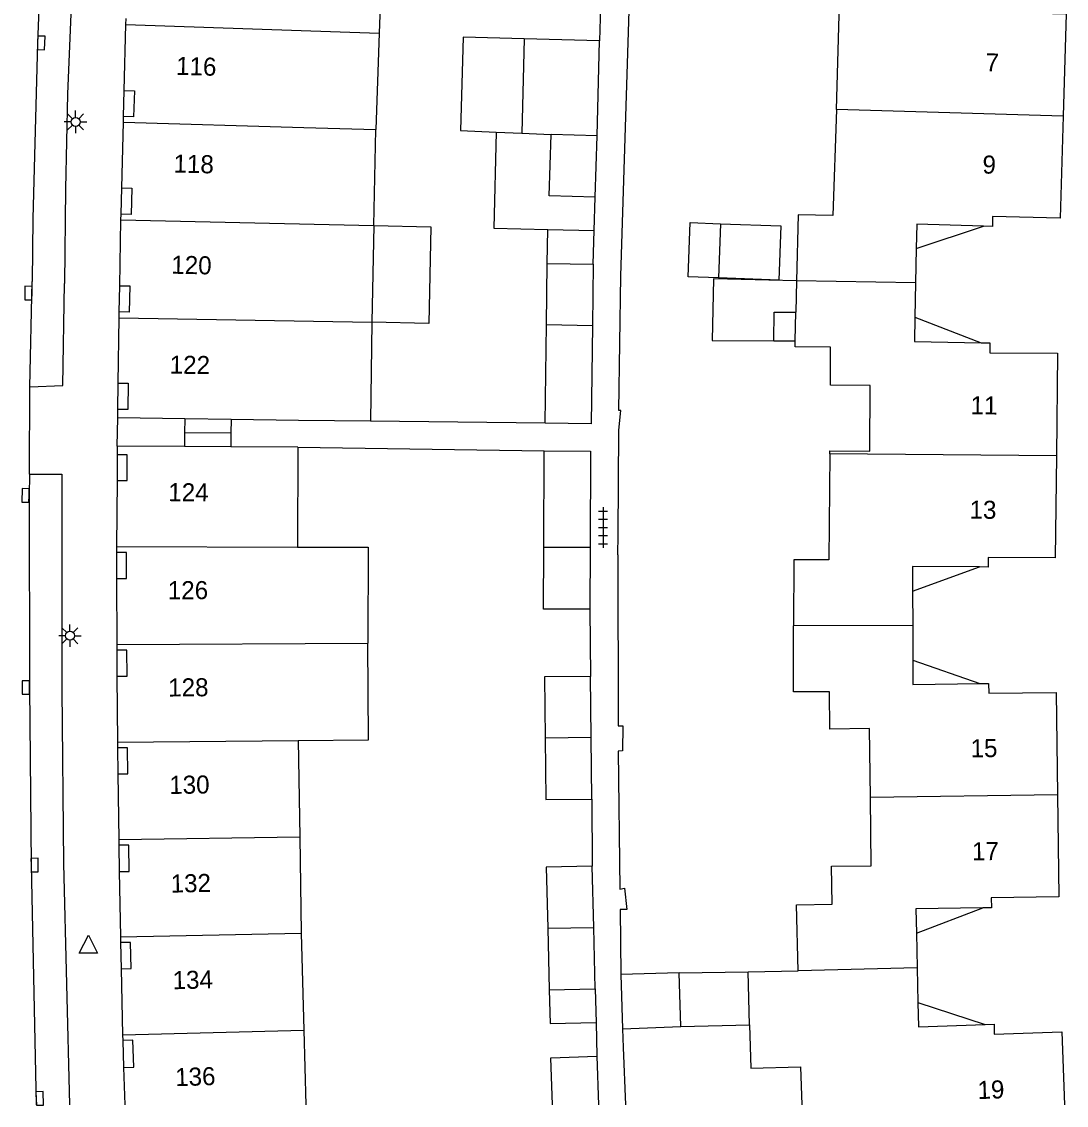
# Model space of a CAD drawing. Extents: x 124000 to 128010, y 398999 to 403000.
# Drawn here: x 126564.4 to 126622.2, y 399000 to 399060 of the extents above; entities that cross this region are included whole.
import ezdxf

# ---------------------------------------------------------------- set-up
doc = ezdxf.new("R2010")
doc.units = 0
for name, color, linetype in [('gg-afsc-erfafscheiding', 7, 'Continuous'), ('gg-afsc-muur', 7, 'Continuous'), ('gg-anno-huisnummerreeks BGT', 7, 'Continuous'), ('gg-bbg-bijgebouw', 7, 'Continuous'), ('gg-bbg-gedigitaliseerde bebouwing', 7, 'Continuous'), ('gg-bbg-gedigitaliseerde bijgebouw', 7, 'Continuous'), ('gg-bbg-hoofdgebouw', 7, 'Continuous'), ('gg-bbg-luifel en loopbrug', 7, 'Continuous'), ('gg-bbg-onder overbouw', 7, 'Continuous'), ('gg-bbg-pand overbouw', 7, 'Continuous'), ('gg-bbg-tussenscheiding', 7, 'Continuous'), ('gg-bbg-tussenscheiding niveau 01', 7, 'Continuous'), ('gg-knt-verharding', 7, 'Continuous'), ('gg-knt-verharding nz', 7, 'Continuous'), ('gt-symb-kolk', 7, 'Continuous'), ('gt-symb-lichtmast', 7, 'Continuous'), ('gt-symb-tegel verharding', 7, 'Continuous'), ('gt-symb-waterafsluiter', 7, 'Continuous')]:
    doc.layers.add(name, color=color, linetype=linetype)

# ---------------------------------------------------------------- blocks, each defined once
blk = doc.blocks.new('gt0-KOLK')
at = {"layer": 'gt-symb-kolk'}
blk.add_lwpolyline([(0, 0), (0.375, 0), (0.375, 0.4), (-0.375, 0.4), (-0.375, 0), (0, 0)], dxfattribs=at)
blk = doc.blocks.new('gt0-WAFSL')
at = {"layer": 'gt-symb-waterafsluiter'}
for p, q in [((-0.5, -0.333), (0, 0.667)), ((0, 0.667), (0.5, -0.333)), ((0.5, -0.333), (-0.5, -0.333))]:
    blk.add_line(p, q, dxfattribs=at)
blk = doc.blocks.new('gt0-LMAST')
at = {"layer": 'gt-symb-lichtmast'}
for p, q in [((-0.005, 0.246), (-0.005, 0.621)), ((-0.182, 0.173), (-0.447, 0.438)), ((0.172, 0.173), (0.437, 0.438)), ((-0.255, -0.004), (-0.63, -0.004)), ((-0.182, -0.181), (-0.447, -0.446)), ((-0.005, -0.254), (-0.005, -0.629)), ((0.437, -0.446), (0.172, -0.181)), ((0.245, -0.004), (0.62, -0.004))]:
    blk.add_line(p, q, dxfattribs=at)
blk.add_circle((-0.005, -0.004), 0.25, dxfattribs=at)
blk = doc.blocks.new('gt0-TEG1')
at = {"layer": 'gt-symb-tegel verharding'}
for p, q in [((-1.125, 0), (1.125, 0)), ((-0.9, -0.25), (-0.9, 0.25)), ((-0.45, -0.25), (-0.45, 0.25)), ((0, -0.25), (0, 0.25)), ((0.45, -0.25), (0.45, 0.25)), ((0.9, -0.25), (0.9, 0.25))]:
    blk.add_line(p, q, dxfattribs=at)

msp = doc.modelspace()

# ---------------------------------------------------------------- linework, layer by layer
at = {"layer": 'gg-afsc-erfafscheiding'}
for p, q in [((126596.442, 399060.81), (126596.39, 399058.933)), ((126597.471, 399037.357), (126597.577, 399038.451)), ((126597.4, 399030.467), (126597.42, 399031.569)), ((126595.856, 399027.447), (126595.89, 399023.725)), ((126597.678, 399020.993), (126597.674, 399019.598)), ((126595.961, 399016.937), (126595.989, 399013.218)), ((126597.779, 399011.998), (126597.898, 399010.824)), ((126596.201, 399004.563), (126596.247, 399002.695)), ((126597.665, 399004.22), (126597.706, 399003.174))]:
    msp.add_line(p, q, dxfattribs=at)
msp.add_lwpolyline([(126597.566, 399045.913), (126598.094, 399062.376), (126598.818, 399078.831)], dxfattribs=at)
at = {"layer": 'gg-afsc-muur'}
for p, q in [((126569.688, 399036.475), (126569.718, 399038.052)), ((126593.379, 399037.745), (126583.718, 399037.871)), ((126597.42, 399031.569), (126597.471, 399037.357)), ((126579.685, 399036.418), (126593.327, 399036.211)), ((126597.706, 399003.174), (126597.826, 399000))]:
    msp.add_line(p, q, dxfattribs=at)
for points in [[(126597.577, 399038.451), (126597.469, 399038.454), (126597.566, 399045.913)], [(126597.4, 399030.467), (126597.42, 399020.989), (126597.678, 399020.993)], [(126597.674, 399019.598), (126597.436, 399019.588), (126597.517, 399011.944), (126597.779, 399011.998)], [(126597.898, 399010.824), (126597.537, 399010.822), (126597.577, 399007.216)]]:
    msp.add_lwpolyline(points, dxfattribs=at)
at = {"layer": 'gg-bbg-bijgebouw'}
for p, q in [((126596.152, 399050.27), (126596.258, 399053.657)), ((126593.452, 399043.207), (126593.498, 399046.6)), ((126593.498, 399046.6), (126596.044, 399046.566)), ((126596.044, 399046.566), (126595.998, 399043.166)), ((126593.379, 399037.745), (126593.452, 399043.207)), ((126593.307, 399030.863), (126593.327, 399036.211)), ((126595.868, 399030.858), (126595.856, 399027.447)), ((126595.925, 399020.337), (126595.89, 399023.725)), ((126595.961, 399016.937), (126595.925, 399020.337)), ((126596.071, 399009.829), (126595.989, 399013.218)), ((126593.526, 399009.778), (126593.609, 399006.369)), ((126596.154, 399006.431), (126596.071, 399009.829)), ((126600.802, 399007.316), (126597.577, 399007.216)), ((126597.577, 399007.216), (126597.665, 399004.22)), ((126600.895, 399004.337), (126600.802, 399007.316)), ((126593.609, 399006.369), (126596.154, 399006.431)), ((126597.665, 399004.22), (126600.895, 399004.337)), ((126596.247, 399002.695), (126596.34, 399000))]:
    msp.add_line(p, q, dxfattribs=at)
for points in [[(126596.152, 399050.27), (126593.608, 399050.349), (126593.714, 399053.73)], [(126595.998, 399043.166), (126595.924, 399037.712), (126593.379, 399037.745)], [(126593.327, 399036.211), (126595.888, 399036.201), (126595.868, 399030.858)], [(126595.856, 399027.447), (126593.294, 399027.456), (126593.307, 399030.863)], [(126595.89, 399023.725), (126593.344, 399023.698), (126593.38, 399020.313)], [(126593.38, 399020.313), (126593.416, 399016.91), (126595.961, 399016.937)], [(126595.989, 399013.218), (126593.444, 399013.157), (126593.526, 399009.778)], [(126593.792, 399000), (126593.702, 399002.608), (126596.247, 399002.695)]]:
    msp.add_lwpolyline(points, dxfattribs=at)
at = {"layer": 'gg-bbg-gedigitaliseerde bebouwing'}
for p, q in [((126584.382, 399064.678), (126584.199, 399059.355)), ((126584.199, 399059.355), (126584.016, 399054.012)), ((126583.9, 399048.692), (126584.016, 399054.012)), ((126583.9, 399048.692), (126583.789, 399043.343)), ((126583.789, 399043.343), (126583.718, 399037.871)), ((126579.685, 399036.418), (126579.678, 399030.893)), ((126579.71, 399020.185), (126579.794, 399014.844)), ((126579.794, 399014.844), (126579.877, 399009.512)), ((126607.388, 399007.428), (126607.303, 399011.087)), ((126579.877, 399009.512), (126580.017, 399004.145)), ((126604.634, 399007.36), (126607.388, 399007.428)), ((126604.706, 399004.431), (126604.634, 399007.36)), ((126580.017, 399004.145), (126580.126, 399000))]:
    msp.add_line(p, q, dxfattribs=at)
for points in [[(126579.678, 399030.893), (126583.583, 399030.884), (126583.571, 399025.562)], [(126579.71, 399020.185), (126583.61, 399020.213), (126583.571, 399025.562)], [(126604.706, 399004.431), (126604.765, 399002.042), (126607.514, 399002.11), (126607.598, 399000)]]:
    msp.add_lwpolyline(points, dxfattribs=at)
at = {"layer": 'gg-bbg-gedigitaliseerde bijgebouw'}
for p, q in [((126592.221, 399059.037), (126592.09, 399053.807)), ((126596.39, 399058.933), (126592.221, 399059.037)), ((126596.258, 399053.657), (126596.39, 399058.933)), ((126592.09, 399053.807), (126593.714, 399053.73)), ((126603.086, 399048.799), (126602.981, 399045.796))]:
    msp.add_line(p, q, dxfattribs=at)
for points in [[(126603.086, 399048.799), (126606.432, 399048.682), (126606.327, 399045.678), (126602.981, 399045.796)], [(126607.305, 399045.639), (126602.713, 399045.742), (126602.637, 399042.323), (126606.052, 399042.312)], [(126606.052, 399042.312), (126606.057, 399043.898), (126607.266, 399043.898)]]:
    msp.add_lwpolyline(points, dxfattribs=at)
at = {"layer": 'gg-bbg-hoofdgebouw'}
for p, q in [((126570.174, 399059.838), (126570.182, 399060.158)), ((126570.08, 399056.176), (126570.174, 399059.838)), ((126570.029, 399054.414), (126570.037, 399054.734)), ((126569.94, 399050.776), (126570.029, 399054.414)), ((126569.896, 399049.003), (126569.902, 399049.323)), ((126569.828, 399045.362), (126569.896, 399049.003)), ((126613.933, 399047.424), (126613.896, 399045.515)), ((126613.896, 399045.515), (126613.859, 399043.616)), ((126569.793, 399043.591), (126569.797, 399043.914)), ((126607.231, 399042.312), (126607.266, 399043.898)), ((126569.75, 399039.97), (126569.793, 399043.591)), ((126569.718, 399038.052), (126569.721, 399038.516)), ((126573.428, 399037.997), (126569.718, 399038.052)), ((126569.688, 399036.475), (126569.685, 399036.006)), ((126573.407, 399036.454), (126569.688, 399036.475)), ((126579.685, 399036.418), (126575.978, 399036.439)), ((126569.688, 399034.57), (126569.655, 399030.915)), ((126569.655, 399030.915), (126569.652, 399030.595)), ((126569.655, 399029.153), (126569.658, 399025.495)), ((126613.731, 399028.458), (126613.736, 399026.547)), ((126613.736, 399026.547), (126613.741, 399024.637)), ((126569.658, 399025.495), (126569.658, 399025.175)), ((126569.673, 399023.739), (126569.698, 399020.089)), ((126569.698, 399020.089), (126569.7, 399019.769)), ((126569.727, 399018.331), (126569.773, 399014.701)), ((126569.773, 399014.701), (126569.777, 399014.381)), ((126569.799, 399012.926), (126569.869, 399009.307)), ((126569.869, 399009.307), (126569.875, 399008.987)), ((126613.94, 399009.511), (126613.982, 399007.593)), ((126569.906, 399007.537), (126569.989, 399003.886)), ((126613.982, 399007.593), (126614.024, 399005.674)), ((126569.989, 399003.886), (126569.996, 399003.566)), ((126570.045, 399002.08), (126570.106, 399000))]:
    msp.add_line(p, q, dxfattribs=at)
for points in [[(126609.525, 399055.113), (126609.677, 399061.003), (126607.715, 399061.061), (126607.872, 399064.718)], [(126618.024, 399061.072), (126618.511, 399061.057), (126618.487, 399060.505), (126622.242, 399060.419), (126622.071, 399054.755)], [(126609.525, 399055.113), (126609.311, 399049.252), (126607.387, 399049.288), (126607.305, 399045.639)], [(126622.071, 399054.755), (126621.901, 399049.098), (126618.153, 399049.194), (126618.15, 399048.648), (126617.657, 399048.663)], [(126617.657, 399048.663), (126613.959, 399048.774), (126613.933, 399047.424)], [(126613.859, 399043.616), (126613.833, 399042.266), (126617.533, 399042.208)], [(126609.15, 399036.062), (126609.152, 399036.22), (126611.361, 399036.208), (126611.379, 399039.84), (126609.186, 399039.857), (126609.191, 399041.953), (126607.223, 399041.98), (126607.231, 399042.312)], [(126617.533, 399042.208), (126618.011, 399042.2), (126618.006, 399041.651), (126621.747, 399041.634), (126621.69, 399035.949)], [(126583.718, 399037.871), (126579.718, 399037.903), (126575.997, 399037.958)], [(126609.15, 399036.062), (126609.092, 399030.175), (126607.147, 399030.19), (126607.144, 399026.53)], [(126621.69, 399035.949), (126621.633, 399030.289), (126617.923, 399030.309), (126617.908, 399029.785), (126617.428, 399029.788)], [(126617.428, 399029.788), (126613.728, 399029.808), (126613.731, 399028.458)], [(126611.391, 399017.03), (126611.336, 399020.85), (126609.146, 399020.799), (126609.124, 399022.876), (126607.141, 399022.865), (126607.144, 399026.53)], [(126613.741, 399024.637), (126613.744, 399023.287), (126617.444, 399023.337)], [(126617.444, 399023.337), (126617.924, 399023.344), (126617.948, 399022.793), (126621.676, 399022.844), (126621.752, 399017.173)], [(126607.303, 399011.087), (126609.277, 399011.112), (126609.234, 399013.22), (126611.439, 399013.242), (126611.391, 399017.03)], [(126621.752, 399017.173), (126621.828, 399011.514), (126618.089, 399011.46), (126618.092, 399010.913), (126617.611, 399010.907)], [(126617.611, 399010.907), (126613.911, 399010.861), (126613.94, 399009.511)], [(126614.024, 399005.674), (126614.054, 399004.324), (126617.752, 399004.446)], [(126617.752, 399004.446), (126618.238, 399004.462), (126618.255, 399003.914), (126621.998, 399004.047), (126622.132, 399000)]]:
    msp.add_lwpolyline(points, dxfattribs=at)
at = {"layer": 'gg-bbg-luifel en loopbrug'}
for p, q in [((126590.677, 399053.874), (126592.09, 399053.807)), ((126596.098, 399048.418), (126596.152, 399050.27)), ((126613.933, 399047.424), (126617.657, 399048.663)), ((126593.498, 399046.6), (126593.524, 399048.482)), ((126593.524, 399048.482), (126596.098, 399048.418)), ((126596.044, 399046.566), (126596.098, 399048.418)), ((126613.859, 399043.616), (126617.533, 399042.208)), ((126606.052, 399042.312), (126607.231, 399042.312)), ((126613.731, 399028.458), (126617.428, 399029.788)), ((126613.741, 399024.637), (126617.444, 399023.337)), ((126613.94, 399009.511), (126617.611, 399010.907)), ((126600.802, 399007.316), (126604.634, 399007.36)), ((126596.154, 399006.431), (126596.201, 399004.563)), ((126614.024, 399005.674), (126617.752, 399004.446)), ((126600.895, 399004.337), (126604.706, 399004.431))]:
    msp.add_line(p, q, dxfattribs=at)
for points in [[(126592.221, 399059.037), (126588.84, 399059.131), (126588.695, 399053.968), (126590.677, 399053.874)], [(126590.677, 399053.874), (126590.545, 399048.556), (126593.524, 399048.482)], [(126583.9, 399048.692), (126587.052, 399048.621), (126586.935, 399043.273), (126583.789, 399043.343)], [(126602.981, 399045.796), (126601.307, 399045.854), (126601.413, 399048.858), (126603.086, 399048.799)], [(126593.609, 399006.369), (126593.654, 399004.501), (126596.201, 399004.563)]]:
    msp.add_lwpolyline(points, dxfattribs=at)
at = {"layer": 'gg-bbg-onder overbouw'}
for p, q in [((126575.997, 399037.958), (126573.428, 399037.997)), ((126575.978, 399036.439), (126573.407, 399036.454))]:
    msp.add_line(p, q, dxfattribs=at)
for points in [[(126570.08, 399056.176), (126570.64, 399056.159), (126570.587, 399054.718), (126570.037, 399054.734)], [(126569.94, 399050.776), (126570.5, 399050.761), (126570.452, 399049.309), (126569.902, 399049.323)], [(126569.828, 399045.362), (126570.388, 399045.35), (126570.347, 399043.902), (126569.797, 399043.914)], [(126569.75, 399039.97), (126570.3, 399039.959), (126570.281, 399038.505), (126569.721, 399038.516)], [(126569.688, 399034.57), (126570.238, 399034.571), (126570.235, 399036.007), (126569.685, 399036.006)], [(126569.655, 399029.153), (126570.205, 399029.154), (126570.202, 399030.596), (126569.652, 399030.595)], [(126569.673, 399023.739), (126570.233, 399023.745), (126570.218, 399025.181), (126569.658, 399025.175)], [(126569.727, 399018.331), (126570.277, 399018.341), (126570.26, 399019.78), (126569.7, 399019.769)], [(126569.799, 399012.926), (126570.359, 399012.934), (126570.337, 399014.389), (126569.777, 399014.381)], [(126569.906, 399007.537), (126570.456, 399007.549), (126570.425, 399008.999), (126569.875, 399008.987)], [(126570.045, 399002.08), (126570.605, 399002.098), (126570.556, 399003.584), (126569.996, 399003.566)]]:
    msp.add_lwpolyline(points, dxfattribs=at)
at = {"layer": 'gg-bbg-pand overbouw'}
for p, q in [((126570.037, 399054.734), (126570.08, 399056.176)), ((126569.902, 399049.323), (126569.94, 399050.776)), ((126569.797, 399043.914), (126569.828, 399045.362)), ((126569.721, 399038.516), (126569.75, 399039.97)), ((126573.428, 399037.997), (126573.417, 399037.225)), ((126575.997, 399037.958), (126575.987, 399037.192)), ((126573.417, 399037.225), (126573.407, 399036.454)), ((126575.987, 399037.192), (126575.978, 399036.439)), ((126569.685, 399036.006), (126569.688, 399034.57)), ((126569.652, 399030.595), (126569.655, 399029.153)), ((126569.658, 399025.175), (126569.673, 399023.739)), ((126569.7, 399019.769), (126569.727, 399018.331)), ((126569.777, 399014.381), (126569.799, 399012.926)), ((126569.875, 399008.987), (126569.906, 399007.537)), ((126569.996, 399003.566), (126570.045, 399002.08))]:
    msp.add_line(p, q, dxfattribs=at)
at = {"layer": 'gg-bbg-tussenscheiding'}
for p, q in [((126570.174, 399059.838), (126584.199, 399059.355)), ((126622.071, 399054.755), (126609.525, 399055.113)), ((126570.029, 399054.414), (126580.024, 399054.13)), ((126580.024, 399054.13), (126584.016, 399054.012)), ((126596.258, 399053.657), (126593.714, 399053.73)), ((126569.896, 399049.003), (126583.9, 399048.692)), ((126607.305, 399045.639), (126607.266, 399043.898)), ((126613.896, 399045.515), (126607.305, 399045.639)), ((126569.793, 399043.591), (126583.789, 399043.343)), ((126593.452, 399043.207), (126595.998, 399043.166)), ((126621.69, 399035.949), (126609.15, 399036.062)), ((126569.655, 399030.915), (126579.678, 399030.893)), ((126595.868, 399030.858), (126593.307, 399030.863)), ((126613.736, 399026.547), (126607.144, 399026.53)), ((126569.658, 399025.495), (126583.571, 399025.562)), ((126569.698, 399020.089), (126579.71, 399020.185)), ((126595.925, 399020.337), (126593.38, 399020.313)), ((126621.752, 399017.173), (126611.391, 399017.03)), ((126569.773, 399014.701), (126579.794, 399014.844)), ((126593.526, 399009.778), (126596.071, 399009.829)), ((126569.869, 399009.307), (126579.877, 399009.512)), ((126613.982, 399007.593), (126607.388, 399007.428)), ((126569.989, 399003.886), (126580.017, 399004.145))]:
    msp.add_line(p, q, dxfattribs=at)
at = {"layer": 'gg-bbg-tussenscheiding niveau 01'}
msp.add_line((126575.987, 399037.192), (126573.417, 399037.225), dxfattribs=at)
at = {"layer": 'gg-knt-verharding'}
msp.add_line((126564.837, 399034.922), (126564.856, 399039.765), dxfattribs=at)
for points in [[(126567.754, 399102.809), (126569.494, 399102.609), (126568.412, 399086.646), (126567.575, 399071.509), (126566.943, 399055.965), (126566.823, 399050.729), (126566.765, 399045.491)], [(126564.856, 399039.765), (126566.686, 399039.832), (126566.765, 399045.491)], [(126564.837, 399034.922), (126566.619, 399034.933), (126566.625, 399023.009), (126566.72, 399013.37), (126567.044, 399000)]]:
    msp.add_lwpolyline(points, dxfattribs=at)
at = {"layer": 'gg-knt-verharding nz'}
msp.add_line((126564.856, 399039.765), (126564.986, 399045.601), dxfattribs=at)
for points in [[(126567.754, 399102.809), (126567.488, 399099.583), (126566.638, 399086.898), (126565.782, 399071.857), (126565.283, 399058.814), (126565.014, 399049.089), (126564.986, 399045.601)], [(126564.837, 399034.922), (126564.807, 399033.744), (126564.831, 399023.115), (126564.915, 399013.279), (126565.206, 399000)]]:
    msp.add_lwpolyline(points, dxfattribs=at)

# ---------------------------------------------------------------- block references
at = {"layer": 'gt-symb-kolk'}
for p, rotation in [((126565.283, 399058.814), -91.94925412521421), ((126564.973, 399044.948), 88.68242937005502), ((126564.807, 399033.744), 88.6251652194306), ((126564.831, 399023.115), 90), ((126564.915, 399013.279), -89.31248364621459), ((126565.197, 399000.351), -87.70709949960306)]:
    msp.add_blockref('gt0-KOLK', p, dxfattribs=dict(at, rotation=rotation))
at = {"layer": 'gt-symb-lichtmast'}
for p in [(126567.39, 399054.441), (126567.077, 399025.986)]:
    msp.add_blockref('gt0-LMAST', p, dxfattribs=at)
at = {"layer": 'gt-symb-tegel verharding', "rotation": -90.00000000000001}
msp.add_blockref('gt0-TEG1', (126596.587, 399031.979), dxfattribs=at)
at = {"layer": 'gt-symb-waterafsluiter'}
msp.add_blockref('gt0-WAFSL', (126568.09, 399008.741), dxfattribs=at)

# ---------------------------------------------------------------- texts
at = {"layer": 'gg-anno-huisnummerreeks BGT'}
for s, rotation, p in [('7', 358.3, (126617.756, 399057.238)), ('116', 358.5, (126572.938, 399057.043)), ('118', 358.6, (126572.797, 399051.635)), ('9', 358.3, (126617.585, 399051.581)), ('120', 358.9, (126572.676, 399046.029)), ('122', 359.3, (126572.591, 399040.495)), ('11', 359.4, (126616.936, 399038.246)), ('124', 359.5, (126572.513, 399033.434)), ('13', 359.4, (126616.878, 399032.467)), ('126', 0.1, (126572.491, 399028.003)), ('128', 0.4, (126572.515, 399022.614)), ('15', 0.7, (126616.946, 399019.246)), ('130', 0.7, (126572.576, 399017.219)), ('17', 0.7, (126617.023, 399013.54)), ('132', 1.1, (126572.656, 399011.754)), ('134', 1.3, (126572.767, 399006.402)), ('136', 1.7, (126572.911, 399001.034)), ('19', 1.9, (126617.342, 399000.32))]:
    msp.add_text(s, height=1, rotation=rotation, dxfattribs=at).set_placement(p)

doc.saveas('drawing.dxf')
